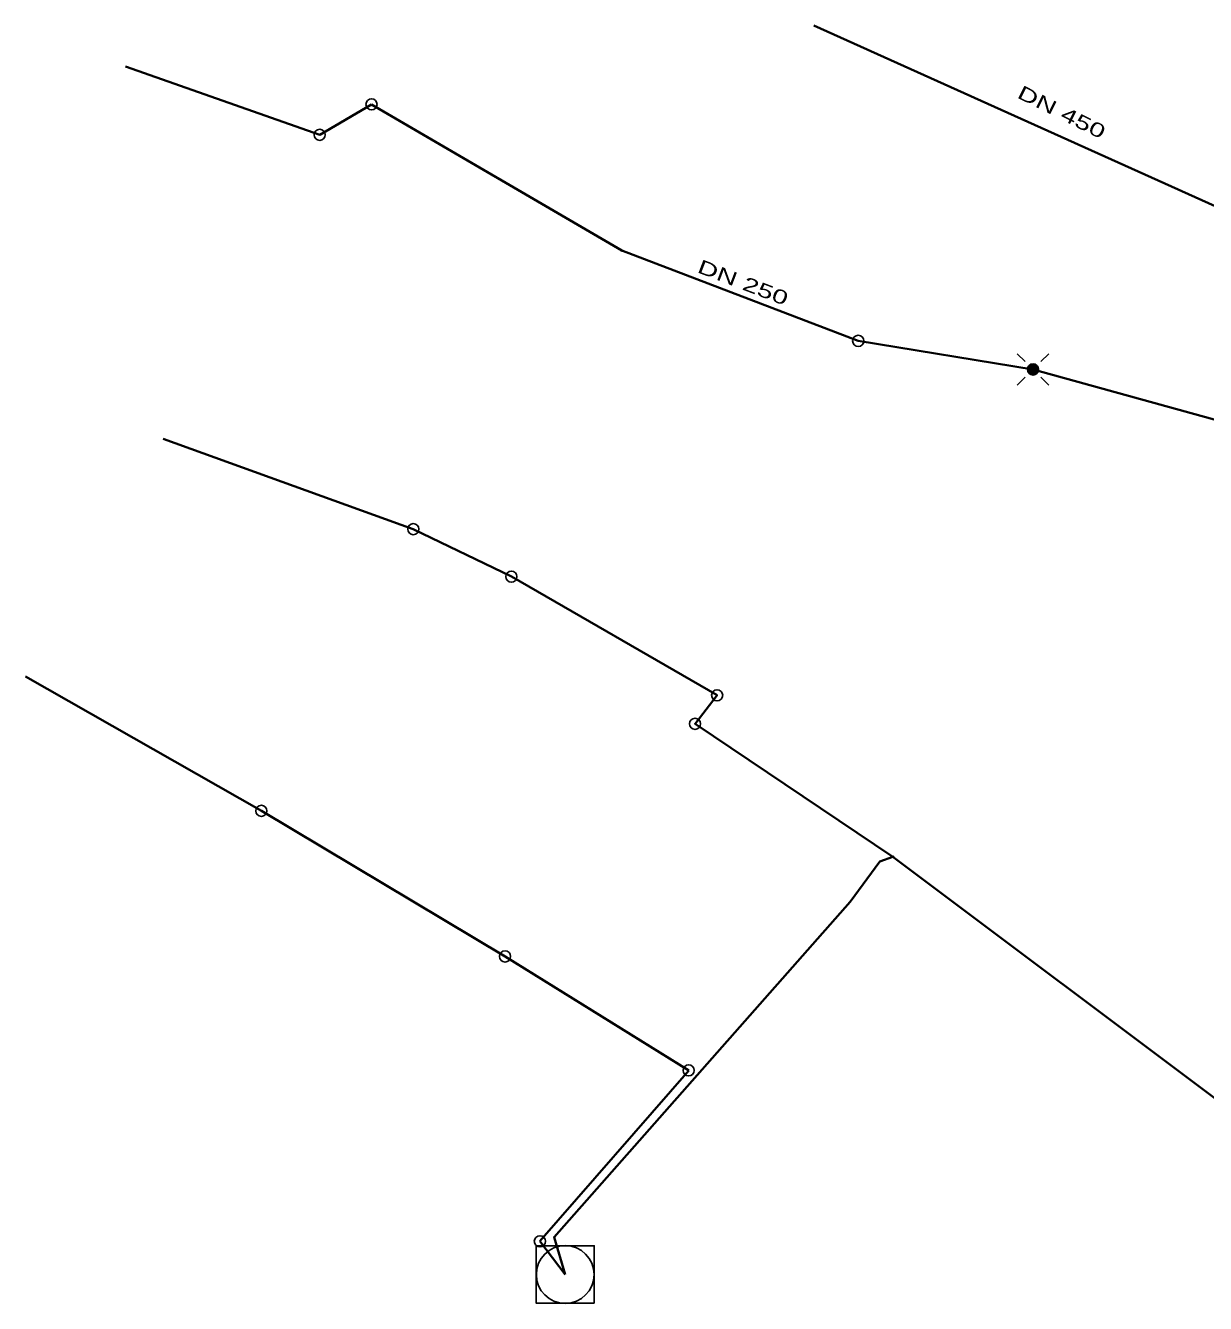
# Model space of a CAD drawing. Extents: x -875105 to -874230, y -1056050 to -1055587.
# Drawn here: x -875105.2 to -874893.5, y -1055847 to -1055617.6 of the extents above; entities that cross this region are included whole.
import ezdxf
from ezdxf.enums import TextEntityAlignment as Align

# ---------------------------------------------------------------- set-up
doc = ezdxf.new("R2010")
doc.units = 0
doc.header["$LTSCALE"] = 0.52
doc.layers.add('26', color=7, linetype='Continuous', lineweight=35)
doc.layers.add('30', color=7, linetype='Continuous', lineweight=25)
doc.layers.add('42', color=7, linetype='Continuous')

msp = doc.modelspace()

# ---------------------------------------------------------------- hatches: boundary and pattern name
at = {"layer": '30'}
msp.add_hatch(color=256, dxfattribs=at).paths.add_polyline_path([(-874925.415, -1055679.357, 1), (-874923.415, -1055679.357, 1)])

# ---------------------------------------------------------------- linework, layer by layer
at = {"layer": '26'}
for p, q in [((-874963.777, -1055617.649), (-874888.135, -1055651.67)), ((-875043.116, -1055631.794), (-874998.219, -1055658.036)), ((-874924.415, -1055679.357), (-874877.971, -1055692.192)), ((-874949.574, -1055766.8), (-874888.859, -1055812.306)), ((-874986.207, -1055805.138), (-875012.901, -1055835.807)), ((-875012.901, -1055835.807), (-875008.357, -1055841.771))]:
    msp.add_line(p, q, dxfattribs=at)
for points in [[(-875087.252, -1055624.976), (-875052.416, -1055637.255), (-875043.116, -1055631.794)], [(-874998.219, -1055658.036), (-874955.782, -1055674.231), (-874924.415, -1055679.357)], [(-875080.488, -1055691.83), (-875035.619, -1055708.017), (-875018.013, -1055716.536)], [(-875018.013, -1055716.536), (-874981.095, -1055737.835), (-874985.071, -1055742.946), (-874949.574, -1055766.8)], [(-875105.194, -1055734.427), (-875062.881, -1055758.565), (-875019.149, -1055784.691), (-874986.207, -1055805.138)], [(-875008.357, -1055841.771), (-875010.371, -1055835.044), (-874957.204, -1055774.914), (-874951.929, -1055767.635), (-874949.574, -1055766.8)]]:
    msp.add_lwpolyline(points, dxfattribs=at)
at = {"layer": '30'}
for p, q in [((-874925.83, -1055677.943), (-874927.243, -1055676.529)), ((-874923.001, -1055677.943), (-874921.587, -1055676.529)), ((-874925.83, -1055680.772), (-874927.243, -1055682.185)), ((-874923.001, -1055680.772), (-874921.587, -1055682.185))]:
    msp.add_line(p, q, dxfattribs=at)
msp.add_lwpolyline([(-875003.153, -1055846.936), (-875003.153, -1055836.607), (-875013.562, -1055836.607), (-875013.562, -1055846.936)], close=True, dxfattribs=at)
for centre, radius in [((-875043.116, -1055631.794), 1), ((-875052.416, -1055637.255), 1), ((-874955.782, -1055674.231), 1), ((-874924.415, -1055679.357), 1), ((-875035.619, -1055708.017), 1), ((-875018.013, -1055716.536), 1), ((-874981.095, -1055737.835), 1), ((-874985.071, -1055742.946), 1), ((-875062.881, -1055758.565), 1), ((-875019.149, -1055784.691), 1), ((-874986.207, -1055805.138), 1), ((-875012.901, -1055835.807), 1), ((-875008.357, -1055841.771), 5.1848)]:
    msp.add_circle(centre, radius, dxfattribs=at)
at = {"layer": '30', "lineweight": 13}
for centre, radius in [((-874998.219, -1055658.036), 0.15), ((-874998.219, -1055658.036), 0.075), ((-874949.574, -1055766.8), 0.15), ((-874949.574, -1055766.8), 0.075)]:
    msp.add_circle(centre, radius, dxfattribs=at)

# ---------------------------------------------------------------- texts
at = {"layer": '42', "width": 1.5}
for s, rotation, p in [('DN 450', 333.608, (-874919.8301, -1055634.2915)), ('DN 250', 339.112, (-874976.8897, -1055664.9099))]:
    msp.add_text(s, height=2.5, rotation=rotation, dxfattribs=at).set_placement(p, align=Align.CENTER)

doc.saveas('drawing.dxf')
